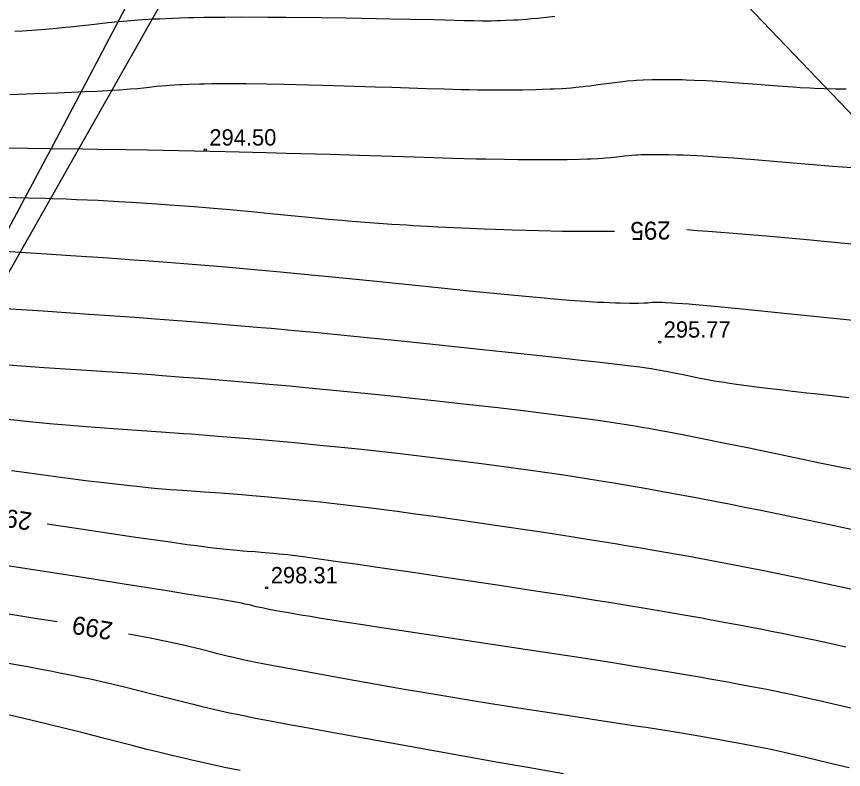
# Model space of a CAD drawing. Extents: x 7477803 to 7478145, y 5500698 to 5500984.
# Drawn here: x 7477901.52 to 7477935.87, y 5500861.45 to 5500892.73 of the extents above; entities that cross this region are included whole.
import ezdxf

# ---------------------------------------------------------------- set-up
doc = ezdxf.new("R2010")
doc.units = 0
for name, color, linetype in [('eWN', 7, 'Continuous'), ('gr_dzialki', 7, 'Continuous'), ('gr_klasy', 7, 'Continuous'), ('pkt_wys', 7, 'Continuous'), ('warst_ciagla', 7, 'Continuous'), ('warst_opis', 7, 'Continuous'), ('warst_pogrub', 7, 'Continuous'), ('warst_przeryw', 7, 'Continuous')]:
    doc.layers.add(name, color=color, linetype=linetype)

# ---------------------------------------------------------------- blocks, each defined once
blk = doc.blocks.new('801_3')
at = {"layer": 'pkt_wys'}
blk.add_circle((0, 0), 0.045, dxfattribs=at)
blk.add_circle((0, 0), 0.045, dxfattribs=at)

msp = doc.modelspace()

# ---------------------------------------------------------------- linework, layer by layer
at = {"layer": 'eWN'}
msp.add_lwpolyline([(7477864.586, 5500830.869), (7477874.504, 5500845.51), (7477886.717, 5500863.094), (7477896.968, 5500876.013), (7477903.181, 5500887.651), (7477907.573, 5500896.009), (7477910.052, 5500901.721), (7477911.094, 5500907.132), (7477899.209, 5500916.554), (7477885.259, 5500927.591), (7477881.972, 5500929.954), (7477875.911, 5500934.547), (7477875.795, 5500934.654)], dxfattribs=at)
at = {"layer": 'gr_dzialki'}
msp.add_lwpolyline([(7477908.77, 5500895.48), (7477894.92, 5500871.04)], dxfattribs=at)
at = {"layer": 'gr_klasy'}
msp.add_lwpolyline([(7477980.49, 5500842.45), (7477927.08, 5500898.2)], dxfattribs=at)
at = {"layer": 'warst_ciagla'}
for points in [[(7477901.244, 5500889.497), (7477902.289, 5500889.532), (7477903.244, 5500889.567), (7477904.365, 5500889.615), (7477904.86, 5500889.639), (7477905.521, 5500889.676), (7477905.784, 5500889.692), (7477906.104, 5500889.714), (7477906.251, 5500889.725), (7477906.55, 5500889.75), (7477906.925, 5500889.788), (7477907.349, 5500889.835), (7477907.559, 5500889.857), (7477907.898, 5500889.885), (7477908.061, 5500889.896), (7477908.288, 5500889.909), (7477908.406, 5500889.915), (7477908.683, 5500889.927), (7477909.127, 5500889.94), (7477909.336, 5500889.944), (7477909.625, 5500889.948), (7477909.775, 5500889.95), (7477910.122, 5500889.951), (7477910.673, 5500889.95), (7477911.064, 5500889.946), (7477911.917, 5500889.933), (7477912.627, 5500889.919), (7477913.67, 5500889.895), (7477914.234, 5500889.88), (7477915.131, 5500889.854), (7477916.424, 5500889.815), (7477917.113, 5500889.792), (7477918.555, 5500889.745), (7477919.283, 5500889.723), (7477919.998, 5500889.705), (7477920.345, 5500889.698), (7477920.685, 5500889.692), (7477921.125, 5500889.687), (7477921.339, 5500889.686), (7477921.755, 5500889.685), (7477922.287, 5500889.688), (7477922.543, 5500889.691), (7477923.094, 5500889.703), (7477923.356, 5500889.711), (7477923.693, 5500889.725), (7477923.855, 5500889.733), (7477924.169, 5500889.75), (7477924.564, 5500889.778), (7477924.751, 5500889.794), (7477924.887, 5500889.807), (7477925.063, 5500889.824), (7477925.148, 5500889.834), (7477925.334, 5500889.856), (7477925.686, 5500889.904), (7477926.136, 5500889.968), (7477926.361, 5500889.999), (7477926.592, 5500890.027), (7477926.711, 5500890.04), (7477926.894, 5500890.058), (7477927.149, 5500890.078), (7477927.28, 5500890.086), (7477927.552, 5500890.1), (7477927.932, 5500890.113), (7477928.13, 5500890.117), (7477928.593, 5500890.119), (7477928.835, 5500890.117), (7477929.167, 5500890.111), (7477929.337, 5500890.106), (7477929.686, 5500890.094), (7477930.169, 5500890.071), (7477930.418, 5500890.058), (7477930.998, 5500890.02), (7477931.297, 5500889.998), (7477931.91, 5500889.95), (7477933.159, 5500889.85), (7477933.776, 5500889.807), (7477934.078, 5500889.788), (7477934.474, 5500889.768), (7477934.669, 5500889.759), (7477935.053, 5500889.745), (7477935.552, 5500889.734), (7477935.797, 5500889.731), (7477935.978, 5500889.73)], [(7477899.036, 5500880.731), (7477902.624, 5500880.502), (7477904.537, 5500880.374), (7477905.176, 5500880.33), (7477906.025, 5500880.269), (7477906.449, 5500880.238), (7477907.295, 5500880.175), (7477908.418, 5500880.088), (7477908.978, 5500880.043), (7477910.234, 5500879.941), (7477910.859, 5500879.888), (7477911.691, 5500879.816), (7477912.107, 5500879.78), (7477912.935, 5500879.705), (7477914.035, 5500879.604), (7477914.583, 5500879.552), (7477915.813, 5500879.433), (7477917.638, 5500879.249), (7477918.819, 5500879.126), (7477921.022, 5500878.892), (7477922.479, 5500878.735), (7477924.139, 5500878.555), (7477924.848, 5500878.477), (7477925.76, 5500878.376), (7477926.692, 5500878.269), (7477927.037, 5500878.228), (7477927.414, 5500878.181), (7477927.597, 5500878.156), (7477927.885, 5500878.11), (7477928.101, 5500878.073), (7477928.412, 5500878.017), (7477928.577, 5500877.985), (7477928.839, 5500877.934), (7477929.212, 5500877.858), (7477929.409, 5500877.817), (7477929.836, 5500877.729), (7477930.082, 5500877.681), (7477930.363, 5500877.63), (7477930.52, 5500877.603), (7477930.688, 5500877.576), (7477930.932, 5500877.538), (7477931.061, 5500877.518), (7477931.337, 5500877.478), (7477931.737, 5500877.423), (7477931.952, 5500877.394), (7477932.47, 5500877.327), (7477933.338, 5500877.22), (7477933.759, 5500877.171), (7477934.353, 5500877.102), (7477934.664, 5500877.067), (7477935.4, 5500876.985), (7477936.097, 5500876.91)], [(7477936.255, 5500871.406), (7477935.292, 5500871.612), (7477933.844, 5500871.918), (7477932.443, 5500872.207), (7477931.839, 5500872.329), (7477931.053, 5500872.485), (7477930.667, 5500872.56), (7477929.819, 5500872.724), (7477928.597, 5500872.952), (7477928.072, 5500873.047), (7477927.391, 5500873.168), (7477927.059, 5500873.225), (7477926.33, 5500873.348), (7477925.975, 5500873.407), (7477925.282, 5500873.517), (7477924.606, 5500873.621), (7477924.161, 5500873.687), (7477923.279, 5500873.815), (7477922.283, 5500873.954), (7477920.948, 5500874.134), (7477920.277, 5500874.22), (7477919.266, 5500874.347), (7477917.909, 5500874.509), (7477917.227, 5500874.588), (7477915.856, 5500874.739), (7477915.166, 5500874.811), (7477914.126, 5500874.916), (7477913.079, 5500875.017), (7477912.611, 5500875.06), (7477911.985, 5500875.116), (7477911.671, 5500875.144), (7477910.962, 5500875.204), (7477909.893, 5500875.291), (7477909.415, 5500875.328), (7477908.776, 5500875.376), (7477908.455, 5500875.399), (7477907.732, 5500875.45), (7477905.538, 5500875.599), (7477904.796, 5500875.653), (7477904.423, 5500875.682), (7477903.753, 5500875.737), (7477903.412, 5500875.767), (7477902.888, 5500875.815), (7477902.061, 5500875.897), (7477901.168, 5500875.993)], [(7477935.974, 5500866.533), (7477935.112, 5500866.722), (7477934.666, 5500866.818), (7477933.974, 5500866.965), (7477933.25, 5500867.113), (7477932.875, 5500867.189), (7477932.491, 5500867.265), (7477931.963, 5500867.367), (7477931.693, 5500867.418), (7477931.14, 5500867.522), (7477930.376, 5500867.662), (7477929.983, 5500867.733), (7477929.07, 5500867.894), (7477928.599, 5500867.975), (7477927.957, 5500868.085), (7477927.629, 5500868.14), (7477926.961, 5500868.251), (7477926.044, 5500868.401), (7477925.575, 5500868.476), (7477924.49, 5500868.648), (7477922.805, 5500868.908), (7477921.676, 5500869.08), (7477919.52, 5500869.402), (7477918.077, 5500869.616), (7477916.42, 5500869.86), (7477915.706, 5500869.964), (7477914.776, 5500870.097), (7477913.804, 5500870.233), (7477913.432, 5500870.283), (7477913.007, 5500870.337), (7477912.79, 5500870.363), (7477912.439, 5500870.4), (7477912.191, 5500870.424), (7477911.858, 5500870.454), (7477911.691, 5500870.468), (7477911.437, 5500870.488), (7477911.097, 5500870.514), (7477910.926, 5500870.526), (7477910.682, 5500870.544), (7477910.531, 5500870.557), (7477910.239, 5500870.586), (7477909.833, 5500870.633), (7477909.575, 5500870.665), (7477908.995, 5500870.74), (7477908.617, 5500870.791), (7477907.9, 5500870.892), (7477906.387, 5500871.11), (7477904.199, 5500871.433), (7477902.799, 5500871.641)], [(7477903.212, 5500867.58), (7477902.285, 5500867.731), (7477900.354, 5500868.042)], [(7477936.11, 5500861.514), (7477935.284, 5500861.717), (7477934.309, 5500861.951), (7477933.876, 5500862.053), (7477933.349, 5500862.172), (7477933.098, 5500862.228), (7477932.724, 5500862.307), (7477932.138, 5500862.425), (7477931.485, 5500862.549), (7477931.169, 5500862.607), (7477930.725, 5500862.686), (7477930.493, 5500862.726), (7477929.945, 5500862.82), (7477929.06, 5500862.968), (7477927.76, 5500863.177), (7477927.059, 5500863.286), (7477923.658, 5500863.806), (7477922.549, 5500863.977), (7477921.136, 5500864.2), (7477920.457, 5500864.309), (7477919.474, 5500864.47), (7477918.229, 5500864.678), (7477917.635, 5500864.78), (7477916.779, 5500864.929), (7477915.223, 5500865.206), (7477913.351, 5500865.545), (7477912.05, 5500865.785), (7477911.466, 5500865.898), (7477911.202, 5500865.953), (7477910.927, 5500866.013), (7477910.535, 5500866.102), (7477910.328, 5500866.151), (7477909.884, 5500866.26), (7477909.635, 5500866.323), (7477909.211, 5500866.432), (7477908.913, 5500866.509), (7477908.735, 5500866.553), (7477908.41, 5500866.629), (7477907.994, 5500866.72), (7477907.743, 5500866.773), (7477907.142, 5500866.893), (7477906.785, 5500866.961), (7477906.17, 5500867.076)]]:
    msp.add_lwpolyline(points, dxfattribs=at)
at = {"layer": 'warst_pogrub'}
for points in [[(7477926.361, 5500883.806), (7477926.059, 5500883.8), (7477925.848, 5500883.798), (7477925.403, 5500883.796), (7477924.696, 5500883.802), (7477924.207, 5500883.809), (7477923.215, 5500883.831), (7477922.12, 5500883.862), (7477921.408, 5500883.886), (7477920.941, 5500883.903), (7477920.026, 5500883.941), (7477919.025, 5500883.989), (7477918.59, 5500884.012), (7477918.019, 5500884.044), (7477917.738, 5500884.06), (7477917.114, 5500884.1), (7477916.204, 5500884.163), (7477915.81, 5500884.193), (7477915.293, 5500884.234), (7477915.039, 5500884.255), (7477914.476, 5500884.305), (7477913.656, 5500884.383), (7477912.067, 5500884.543), (7477911.28, 5500884.619), (7477910.232, 5500884.714), (7477909.708, 5500884.759), (7477908.923, 5500884.823), (7477907.878, 5500884.902), (7477907.356, 5500884.939), (7477906.304, 5500885.008), (7477905.763, 5500885.04), (7477904.917, 5500885.085), (7477904.013, 5500885.125), (7477903.591, 5500885.142), (7477903.011, 5500885.163), (7477902.713, 5500885.172), (7477902.022, 5500885.194), (7477900.935, 5500885.222)], [(7477937.06, 5500883.2), (7477935.215, 5500883.373), (7477934.218, 5500883.465), (7477932.663, 5500883.602), (7477931.127, 5500883.73), (7477930.258, 5500883.799), (7477929.809, 5500883.834), (7477929.36, 5500883.866)], [(7477910.812, 5500861.404), (7477910.167, 5500861.537), (7477909.493, 5500861.684), (7477909.181, 5500861.754), (7477908.752, 5500861.852), (7477908.532, 5500861.903), (7477908.026, 5500862.023), (7477907.317, 5500862.195), (7477906.939, 5500862.289), (7477906.33, 5500862.443), (7477905.29, 5500862.711), (7477904.188, 5500862.998), (7477903.543, 5500863.161), (7477902.815, 5500863.34), (7477902.416, 5500863.436), (7477901.539, 5500863.64), (7477901.057, 5500863.749)]]:
    msp.add_lwpolyline(points, dxfattribs=at)
at = {"layer": 'warst_przeryw'}
for points in [[(7477901.455, 5500892.124), (7477901.766, 5500892.144), (7477902.165, 5500892.171), (7477902.358, 5500892.185), (7477902.73, 5500892.213), (7477903.198, 5500892.252), (7477903.421, 5500892.272), (7477903.891, 5500892.318), (7477904.112, 5500892.342), (7477904.531, 5500892.39), (7477905.334, 5500892.483), (7477905.751, 5500892.526), (7477905.969, 5500892.546), (7477906.273, 5500892.571), (7477906.43, 5500892.583), (7477906.755, 5500892.605), (7477907.209, 5500892.631), (7477907.445, 5500892.643), (7477907.999, 5500892.666), (7477908.288, 5500892.676), (7477908.685, 5500892.688), (7477908.888, 5500892.693), (7477909.306, 5500892.701), (7477909.884, 5500892.71), (7477910.183, 5500892.713), (7477910.877, 5500892.716), (7477911.969, 5500892.713), (7477912.712, 5500892.707), (7477914.176, 5500892.69), (7477915.206, 5500892.676), (7477916.471, 5500892.655), (7477917.058, 5500892.644), (7477917.879, 5500892.628), (7477918.867, 5500892.605), (7477919.314, 5500892.593), (7477920.126, 5500892.57), (7477920.503, 5500892.562), (7477920.872, 5500892.558), (7477921.055, 5500892.558), (7477921.239, 5500892.56), (7477921.484, 5500892.564), (7477921.607, 5500892.568), (7477921.854, 5500892.576), (7477922.184, 5500892.593), (7477922.35, 5500892.603), (7477922.724, 5500892.63), (7477922.911, 5500892.646), (7477923.162, 5500892.669), (7477923.288, 5500892.682), (7477923.541, 5500892.71), (7477923.878, 5500892.752)], [(7477936.603, 5500886.42), (7477935.834, 5500886.473), (7477935.434, 5500886.504), (7477934.616, 5500886.572), (7477932.968, 5500886.714), (7477932.178, 5500886.78), (7477931.799, 5500886.811), (7477931.314, 5500886.847), (7477931.079, 5500886.864), (7477930.627, 5500886.894), (7477930.057, 5500886.928), (7477929.787, 5500886.943), (7477929.214, 5500886.968), (7477928.946, 5500886.978), (7477928.608, 5500886.987), (7477928.447, 5500886.99), (7477928.142, 5500886.993), (7477927.769, 5500886.99), (7477927.597, 5500886.986), (7477927.474, 5500886.982), (7477927.319, 5500886.975), (7477927.245, 5500886.97), (7477927.087, 5500886.959), (7477926.794, 5500886.931), (7477926.21, 5500886.867), (7477925.987, 5500886.847), (7477925.865, 5500886.837), (7477925.669, 5500886.825), (7477925.379, 5500886.81), (7477925.223, 5500886.803), (7477924.887, 5500886.793), (7477924.39, 5500886.782), (7477924.12, 5500886.779), (7477923.463, 5500886.776), (7477923.108, 5500886.777), (7477922.608, 5500886.78), (7477922.346, 5500886.783), (7477921.798, 5500886.791), (7477921.02, 5500886.805), (7477920.609, 5500886.814), (7477919.636, 5500886.838), (7477918.049, 5500886.885), (7477915.755, 5500886.958), (7477914.556, 5500886.995), (7477912.721, 5500887.047), (7477911.891, 5500887.069), (7477910.772, 5500887.096), (7477910.207, 5500887.11), (7477908.922, 5500887.138), (7477906.959, 5500887.176), (7477906.073, 5500887.191), (7477904.879, 5500887.21), (7477904.276, 5500887.219), (7477902.906, 5500887.238), (7477901.054, 5500887.262)], [(7477936.415, 5500880.093), (7477933.679, 5500880.373), (7477931.507, 5500880.589), (7477930.368, 5500880.697), (7477929.883, 5500880.741), (7477929.451, 5500880.777), (7477928.955, 5500880.815), (7477928.742, 5500880.829), (7477928.465, 5500880.845), (7477928.359, 5500880.849), (7477928.233, 5500880.853), (7477928.177, 5500880.854), (7477928.067, 5500880.854), (7477927.941, 5500880.848), (7477927.731, 5500880.83), (7477927.595, 5500880.822), (7477927.36, 5500880.817), (7477927.221, 5500880.817), (7477926.983, 5500880.818), (7477926.614, 5500880.825), (7477926.407, 5500880.83), (7477925.935, 5500880.846), (7477925.652, 5500880.859), (7477925.14, 5500880.89), (7477924.5, 5500880.938), (7477924.173, 5500880.964), (7477923.695, 5500881.005), (7477923.439, 5500881.028), (7477922.819, 5500881.084), (7477921.778, 5500881.183), (7477920.181, 5500881.342), (7477919.294, 5500881.433), (7477916.335, 5500881.74), (7477914.767, 5500881.898), (7477913.193, 5500882.05), (7477912.494, 5500882.115), (7477911.563, 5500882.2), (7477911.097, 5500882.241), (7477910.05, 5500882.331), (7477908.48, 5500882.459), (7477907.783, 5500882.514), (7477906.854, 5500882.584), (7477906.389, 5500882.618), (7477905.345, 5500882.692), (7477903.786, 5500882.797), (7477902.765, 5500882.862), (7477900.823, 5500882.979)], [(7477936.311, 5500873.895), (7477935.785, 5500873.998), (7477935.516, 5500874.051), (7477934.893, 5500874.177), (7477933.922, 5500874.38), (7477932.605, 5500874.659), (7477931.96, 5500874.795), (7477931.032, 5500874.988), (7477929.87, 5500875.221), (7477929.321, 5500875.328), (7477928.54, 5500875.475), (7477928.209, 5500875.536), (7477927.782, 5500875.613), (7477927.575, 5500875.649), (7477927.125, 5500875.726), (7477926.484, 5500875.829), (7477926.06, 5500875.894), (7477925.771, 5500875.936), (7477925.158, 5500876.022), (7477924.386, 5500876.123), (7477923.212, 5500876.27), (7477922.562, 5500876.349), (7477921.51, 5500876.472), (7477919.961, 5500876.647), (7477919.125, 5500876.74), (7477917.337, 5500876.932), (7477916.402, 5500877.03), (7477914.97, 5500877.175), (7477913.523, 5500877.314), (7477912.876, 5500877.373), (7477912.011, 5500877.451), (7477911.577, 5500877.489), (7477910.598, 5500877.572), (7477909.12, 5500877.692), (7477908.46, 5500877.743), (7477907.577, 5500877.809), (7477907.134, 5500877.842), (7477906.134, 5500877.912), (7477904.632, 5500878.013), (7477902.67, 5500878.142), (7477901.73, 5500878.206), (7477900.391, 5500878.304)], [(7477901.309, 5500873.88), (7477901.947, 5500873.79), (7477902.761, 5500873.677), (7477903.152, 5500873.625), (7477903.993, 5500873.514), (7477904.394, 5500873.463), (7477904.907, 5500873.399), (7477905.155, 5500873.369), (7477905.632, 5500873.313), (7477906.232, 5500873.247), (7477906.516, 5500873.216), (7477907.116, 5500873.157), (7477907.397, 5500873.132), (7477907.923, 5500873.088), (7477908.413, 5500873.051), (7477909.329, 5500872.988), (7477909.999, 5500872.94), (7477910.886, 5500872.872), (7477911.326, 5500872.836), (7477911.983, 5500872.78), (7477912.852, 5500872.7), (7477913.283, 5500872.658), (7477914.151, 5500872.569), (7477914.603, 5500872.52), (7477915.329, 5500872.435), (7477916.134, 5500872.336), (7477917.335, 5500872.18), (7477917.991, 5500872.092), (7477919.044, 5500871.946), (7477920.578, 5500871.728), (7477921.399, 5500871.609), (7477923.141, 5500871.35), (7477924.044, 5500871.213), (7477925.41, 5500870.998), (7477925.864, 5500870.925), (7477926.467, 5500870.826), (7477926.768, 5500870.776), (7477927.367, 5500870.675), (7477928.163, 5500870.537), (7477928.558, 5500870.468), (7477929.445, 5500870.309), (7477929.886, 5500870.228), (7477930.471, 5500870.119), (7477930.763, 5500870.064), (7477931.345, 5500869.953), (7477932.116, 5500869.803), (7477932.5, 5500869.727), (7477933.36, 5500869.553), (7477934.633, 5500869.288), (7477935.46, 5500869.112), (7477937.023, 5500868.772)], [(7477936.539, 5500863.92), (7477935.454, 5500864.172), (7477934.925, 5500864.293), (7477934.229, 5500864.447), (7477933.878, 5500864.524), (7477933.334, 5500864.638), (7477932.758, 5500864.755), (7477932.455, 5500864.815), (7477932.138, 5500864.876), (7477931.697, 5500864.959), (7477931.467, 5500865.002), (7477930.991, 5500865.089), (7477930.32, 5500865.209), (7477929.969, 5500865.27), (7477929.143, 5500865.412), (7477927.806, 5500865.635), (7477927.175, 5500865.737), (7477926.297, 5500865.878), (7477925.843, 5500865.95), (7477924.784, 5500866.116), (7477923.114, 5500866.372), (7477919.815, 5500866.87), (7477918.364, 5500867.089), (7477916.702, 5500867.341), (7477915.987, 5500867.45), (7477915.062, 5500867.593), (7477914.1, 5500867.743), (7477913.737, 5500867.801), (7477913.328, 5500867.868), (7477912.827, 5500867.955), (7477912.311, 5500868.048), (7477911.953, 5500868.115), (7477911.72, 5500868.161), (7477911.479, 5500868.215), (7477911.198, 5500868.286), (7477911.097, 5500868.311), (7477911.026, 5500868.327), (7477910.873, 5500868.358), (7477910.486, 5500868.428), (7477909.848, 5500868.536), (7477908.584, 5500868.742), (7477907.775, 5500868.871), (7477906.341, 5500869.099), (7477904.015, 5500869.463), (7477902.675, 5500869.672), (7477899.7, 5500870.136)], [(7477901.197, 5500865.867), (7477902.065, 5500865.71), (7477902.478, 5500865.633), (7477903.005, 5500865.532), (7477903.259, 5500865.483), (7477903.747, 5500865.386), (7477904.358, 5500865.261), (7477904.647, 5500865.2), (7477905.253, 5500865.066), (7477905.535, 5500865.001), (7477906.06, 5500864.875), (7477906.542, 5500864.754), (7477907.418, 5500864.527), (7477908.032, 5500864.369), (7477908.808, 5500864.176), (7477909.177, 5500864.087), (7477909.707, 5500863.962), (7477910.371, 5500863.812), (7477910.685, 5500863.745), (7477911.139, 5500863.651), (7477911.449, 5500863.589), (7477912.148, 5500863.456), (7477912.786, 5500863.337), (7477913.807, 5500863.148), (7477914.391, 5500863.041), (7477917.619, 5500862.457), (7477920.23, 5500861.99), (7477921.533, 5500861.759), (7477922.756, 5500861.544), (7477924.244, 5500861.285)]]:
    msp.add_lwpolyline(points, dxfattribs=at)

# ---------------------------------------------------------------- block references
at = {"layer": 'pkt_wys', "rotation": 0.0626175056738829}
for p in [(7477909.366, 5500887.187), (7477928.235, 5500879.207), (7477911.916, 5500869)]:
    msp.add_blockref('801_3', p, dxfattribs=at)

# ---------------------------------------------------------------- texts
at = {"layer": 'pkt_wys'}
for s, p in [('294.50', (7477909.535, 5500887.371)), ('295.77', (7477928.404, 5500879.392)), ('298.31', (7477912.085, 5500869.184))]:
    msp.add_text(s, height=0.68, rotation=0.0626, dxfattribs=at).set_placement(p)
at = {"layer": 'warst_opis'}
for s, rotation, p in [('295', 181.1503, (7477928.689, 5500884.228)), ('298', 171.2409, (7477902.2, 5500872.113)), ('299', 170.3277, (7477905.563, 5500867.56))]:
    msp.add_text(s, height=0.75, rotation=rotation, dxfattribs=at).set_placement(p)

doc.saveas('drawing.dxf')
